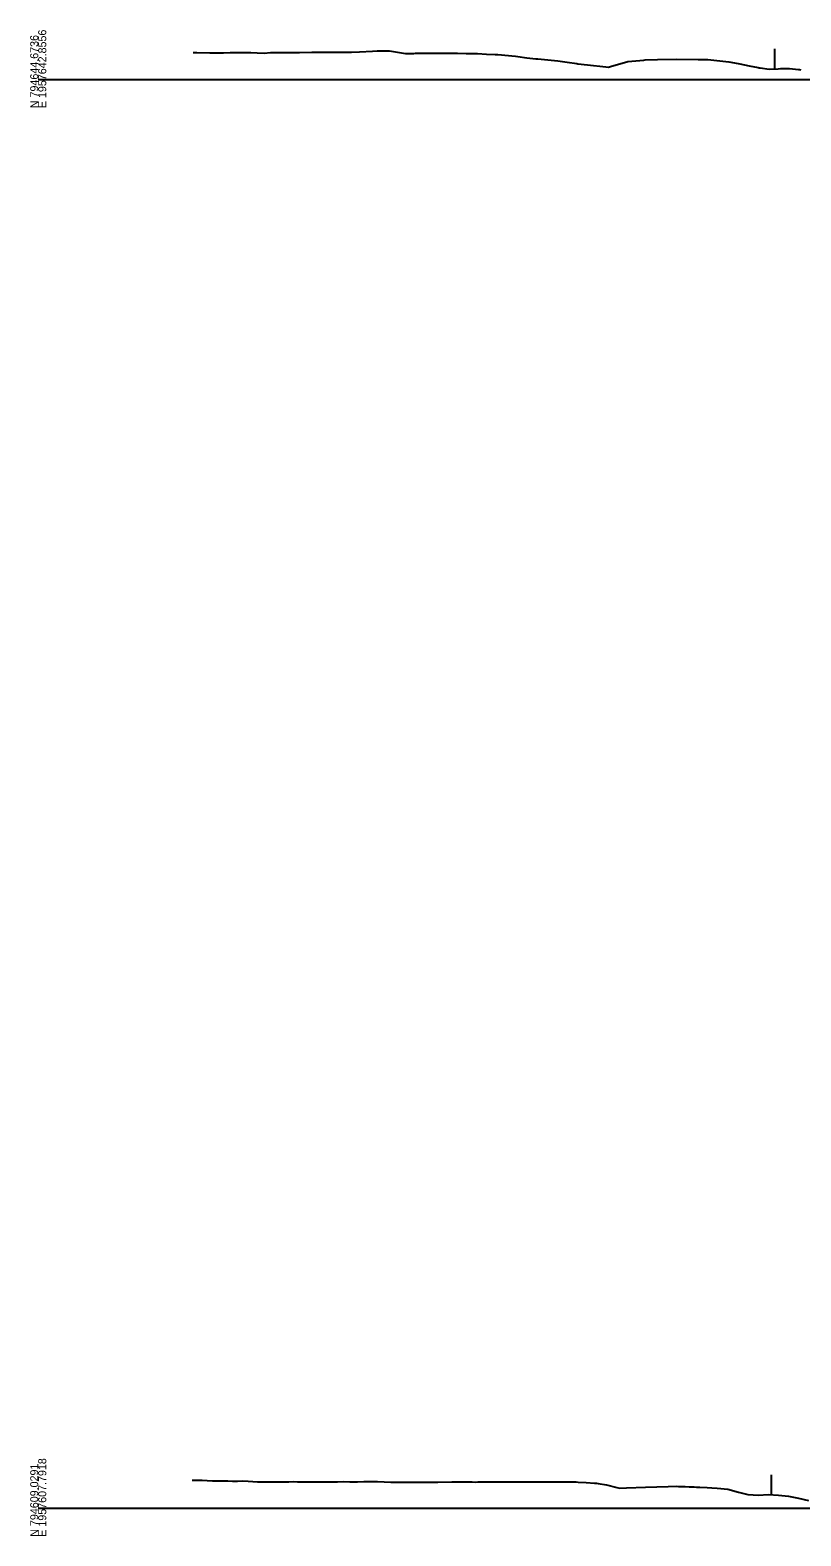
# Model space of a CAD drawing. Extents: x -4026 to 9638, y -10 to 19609.
# Drawn here: x -3003 to -2733, y 15490 to 16017 of the extents above; entities that cross this region are included whole.
import ezdxf

# ---------------------------------------------------------------- set-up
doc = ezdxf.new("R2010")
doc.units = 0
for name, color, linetype in [('Default', 7, 'Continuous'), ('RD_EX_Fence_Other', 7, 'Continuous'), ('RD_GPK_XS_Cell', 7, 'Continuous'), ('RD_XS_ExGround', 7, 'Continuous')]:
    doc.layers.add(name, color=color, linetype=linetype)

msp = doc.modelspace()

# ---------------------------------------------------------------- linework, layer by layer
at = {"layer": 'RD_EX_Fence_Other'}
for p, q in [((-2742.45, 16010.71), (-2742.45, 16003.71)), ((-2743.59, 15511.71), (-2743.59, 15504.71))]:
    msp.add_line(p, q, dxfattribs=at)
at = {"layer": 'RD_GPK_XS_Cell'}
for p, q in [((-3000, 16000), (-2650, 16000)), ((-3000, 15500), (-2650, 15500))]:
    msp.add_line(p, q, dxfattribs=at)
at = {"layer": 'RD_XS_ExGround'}
for points in [[(-2945.75, 16009.44), (-2944.46, 16009.43), (-2939.93, 16009.41), (-2938.68, 16009.4), (-2937.45, 16009.39), (-2935.14, 16009.34), (-2932.8, 16009.45), (-2930.43, 16009.52), (-2925.67, 16009.47), (-2923.42, 16009.41), (-2921, 16009.28), (-2918.77, 16009.53), (-2914.44, 16009.48), (-2912.9, 16009.48), (-2908.57, 16009.49), (-2904.31, 16009.6), (-2895.06, 16009.62), (-2890.43, 16009.63), (-2887.55, 16009.74), (-2883.07, 16009.94), (-2881.46, 16010.1), (-2878.11, 16010.1), (-2877.54, 16010.09), (-2877.14, 16010.05), (-2871.5, 16009.18), (-2868.63, 16009.19), (-2867.97, 16009.2), (-2867.31, 16009.21), (-2864.43, 16009.23), (-2861.5, 16009.25), (-2860.89, 16009.24), (-2860.29, 16009.25), (-2854.37, 16009.22), (-2853.82, 16009.22), (-2853.28, 16009.23), (-2850.29, 16009.18), (-2847.24, 16009.18), (-2846.75, 16009.17), (-2846.27, 16009.16), (-2843.22, 16008.94), (-2840.12, 16008.83), (-2839.68, 16008.81), (-2839.25, 16008.79), (-2832.99, 16008.17), (-2832.24, 16008.1), (-2829.07, 16007.66), (-2825.86, 16007.31), (-2825.54, 16007.28), (-2825.23, 16007.25), (-2818.21, 16006.53), (-2814.93, 16006.08), (-2811.6, 16005.58), (-2811.2, 16005.51), (-2807.86, 16005.13), (-2801.36, 16004.47), (-2800.53, 16004.31), (-2799.75, 16004.53), (-2793.72, 16006.28), (-2788.12, 16006.85), (-2787.67, 16006.89), (-2783.33, 16007), (-2776.71, 16007.17), (-2769.13, 16007.07), (-2766.06, 16007.03), (-2765.72, 16007), (-2758.36, 16006.22), (-2755.09, 16005.63), (-2754.56, 16005.52), (-2751.29, 16004.78), (-2748.08, 16004.22), (-2747.75, 16004.15), (-2747.43, 16004.1), (-2744.22, 16003.6), (-2741.06, 16003.79), (-2740.3, 16003.85), (-2737.15, 16003.93), (-2734.05, 16003.55), (-2733.61, 16003.5), (-2733.17, 16003.4)], [(-2946.16, 15509.84), (-2944.37, 15509.83), (-2942.63, 15509.78), (-2940.85, 15509.69), (-2939.09, 15509.59), (-2937.36, 15509.59), (-2933.72, 15509.56), (-2932.02, 15509.47), (-2930.34, 15509.51), (-2928.48, 15509.58), (-2926.59, 15509.46), (-2924.95, 15509.37), (-2923.33, 15509.28), (-2919.46, 15509.27), (-2916.31, 15509.26), (-2914.34, 15509.23), (-2912.33, 15509.25), (-2910.8, 15509.31), (-2909.3, 15509.26), (-2905.2, 15509.19), (-2902.29, 15509.21), (-2898.07, 15509.18), (-2895.27, 15509.19), (-2893.13, 15509.33), (-2890.94, 15509.22), (-2889.59, 15509.23), (-2888.26, 15509.21), (-2886.05, 15509.31), (-2883.81, 15509.36), (-2881.25, 15509.34), (-2876.68, 15509.13), (-2875.45, 15509.13), (-2874.23, 15509.12), (-2871.91, 15509.08), (-2869.55, 15509.11), (-2868.38, 15509.11), (-2867.22, 15509.11), (-2864.84, 15509.09), (-2862.42, 15509.11), (-2861.31, 15509.13), (-2860.21, 15509.14), (-2855.29, 15509.19), (-2853.19, 15509.19), (-2850.7, 15509.18), (-2848.16, 15509.17), (-2847.16, 15509.16), (-2846.18, 15509.17), (-2843.63, 15509.2), (-2841.03, 15509.24), (-2840.09, 15509.25), (-2839.16, 15509.24), (-2833.9, 15509.21), (-2832.15, 15509.21), (-2829.48, 15509.2), (-2826.77, 15509.2), (-2825.95, 15509.2), (-2825.14, 15509.2), (-2822.41, 15509.23), (-2819.64, 15509.24), (-2818.12, 15509.25), (-2815.34, 15509.24), (-2812.51, 15509.18), (-2811.81, 15509.17), (-2811.11, 15509.14), (-2808.27, 15508.99), (-2805.38, 15508.77), (-2804.73, 15508.73), (-2804.1, 15508.64), (-2801.2, 15508.19), (-2797.52, 15507.23), (-2796.55, 15506.98), (-2794.15, 15507.07), (-2787.57, 15507.33), (-2779.63, 15507.56), (-2776.83, 15507.65), (-2776.03, 15507.62), (-2773.7, 15507.54), (-2772.25, 15507.48), (-2771.25, 15507.45), (-2770.52, 15507.42), (-2769.74, 15507.39), (-2769.35, 15507.38), (-2768.55, 15507.35), (-2765.92, 15507.24), (-2764.3, 15507.12), (-2762.46, 15506.96), (-2758.77, 15506.65), (-2755, 15505.56), (-2751.7, 15504.8), (-2747.99, 15504.51), (-2744.63, 15504.75), (-2740.97, 15504.59), (-2737.56, 15504.22), (-2733.96, 15503.55), (-2730.49, 15502.65)]]:
    msp.add_lwpolyline(points, dxfattribs=at)

# ---------------------------------------------------------------- texts
at = {"layer": 'Default'}
for p in [(-3000, 16000), (-3000, 15500)]:
    msp.add_text('-', height=0.0001, dxfattribs=at).set_placement(p)
at = {"layer": 'RD_GPK_XS_Cell'}
for s, p in [('E 1957642.8556', (-2997.2, 15990)), ('N 794644.6736', (-3000, 15990)), ('N 794609.0291', (-3000, 15490)), ('E 1957607.7918', (-2997.2, 15490))]:
    msp.add_text(s, height=2.8, rotation=90, dxfattribs=at).set_placement(p)

doc.saveas('drawing.dxf')
